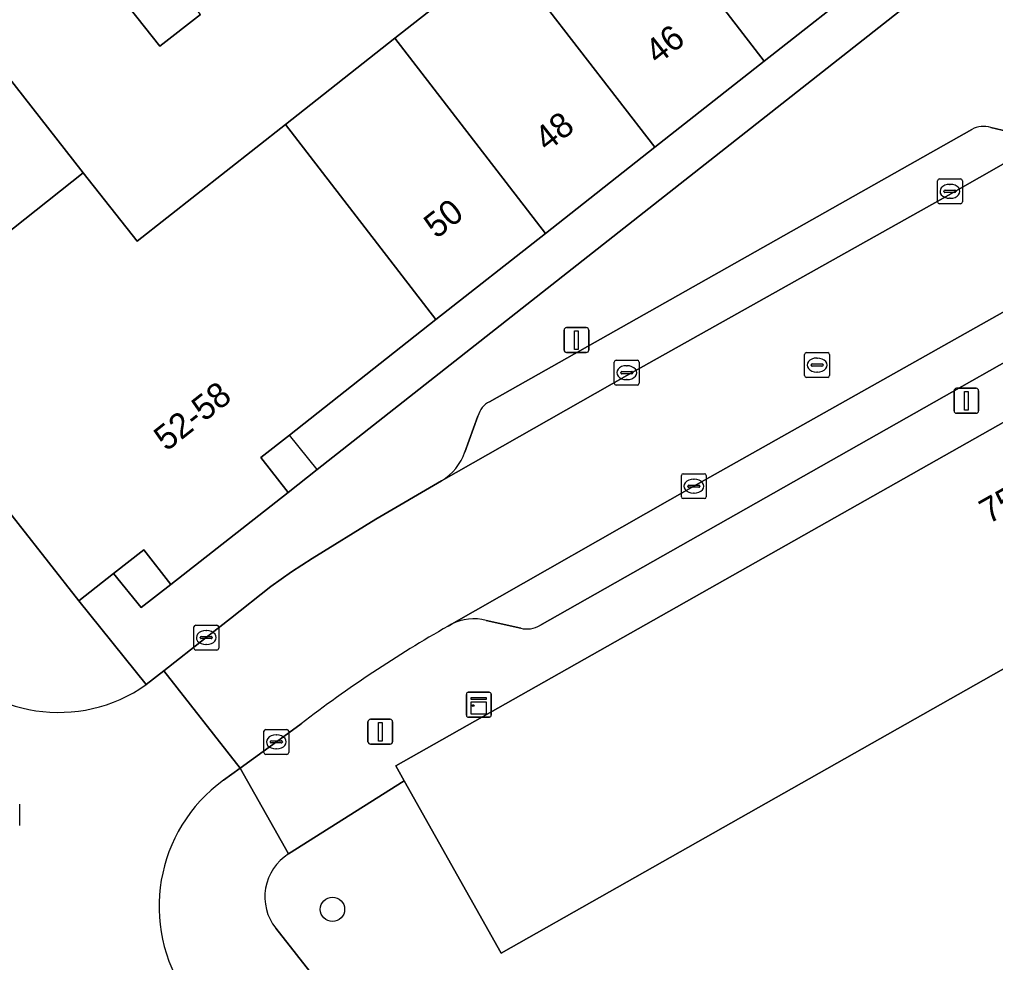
# Model space of a CAD drawing. Extents: x 160377 to 161131, y 383938 to 384853.
# Drawn here: x 160793.66 to 160832.91, y 384332.45 to 384370.35 of the extents above; entities that cross this region are included whole.
import ezdxf

# ---------------------------------------------------------------- set-up
doc = ezdxf.new("R2010")
doc.units = 0
for name, color, linetype in [('IMGEO_Boom', 7, 'Continuous'), ('IMGEO_Erf', 7, 'Continuous'), ('IMGEO_Kast', 7, 'Continuous'), ('IMGEO_Kolk', 7, 'Continuous'), ('IMGEO_Lichtmast', 7, 'Continuous'), ('IMGEO_Pand', 7, 'Continuous'), ('IMGEO_Pand_nummerreeks', 7, 'Continuous'), ('IMGEO_Pand_overbouw', 7, 'Continuous'), ('IMGEO_Parkeervlak_open', 7, 'Continuous'), ('IMGEO_Rijbaan_lokaal_open', 7, 'Continuous'), ('IMGEO_Rioolput', 7, 'Continuous'), ('IMGEO_Voetpad_open', 7, 'Continuous')]:
    doc.layers.add(name, color=color, linetype=linetype)

msp = doc.modelspace()

# ---------------------------------------------------------------- linework, layer by layer
at = {"layer": 'IMGEO_Boom'}
msp.add_circle((160806.245, 384334.579), 0.489, dxfattribs=at)
at = {"layer": 'IMGEO_Erf'}
for points in [[(160833.751, 384374.399), (160832.651, 384375.795), (160828.01, 384372.142), (160823.609, 384368.678), (160819.208, 384365.214), (160814.808, 384361.751), (160810.407, 384358.287), (160804.513, 384353.647), (160803.366, 384352.745), (160804.464, 384351.34), (160805.632, 384352.26)], [(160798.654, 384349.037), (160797.435, 384348.078), (160798.55, 384346.709), (160799.746, 384347.64)]]:
    msp.add_lwpolyline(points, close=True, dxfattribs=at)
for points in [[(160792.762, 384368.592), (160796.225, 384364.19), (160798.39, 384361.439), (160804.353, 384366.133), (160808.754, 384369.597), (160813.155, 384373.06)], [(160800.939, 384370.558), (160799.307, 384369.274), (160797.763, 384371.239)], [(160864.012, 384361.665), (160817.378, 384335.283), (160813.026, 384332.821), (160809.131, 384339.748), (160804.478, 384336.81)], [(160803.961, 384333.818), (160807.286, 384329.584), (160806.969, 384329.33), (160807.38, 384328.806), (160807.698, 384329.059), (160810.129, 384325.962), (160809.812, 384325.71), (160810.233, 384325.182), (160810.55, 384325.434), (160823.97, 384308.474), (160823.653, 384308.221), (160824.106, 384307.637), (160824.656, 384308.075), (160824.527, 384308.24), (160824.985, 384308.54), (160827.264, 384305.335), (160831.604, 384307.819), (160838.184, 384311.586)]]:
    msp.add_lwpolyline(points, dxfattribs=at)
msp.add_arc((160805.571, 384335.08), 2.046, 122.2944, 218.0984, dxfattribs=at)
at = {"layer": 'IMGEO_Kast'}
for p, q in [((160811.628, 384342.381), (160811.628, 384343.222)), ((160811.628, 384343.222), (160811.628, 384342.381)), ((160811.703, 384343.306), (160812.544, 384343.306)), ((160812.544, 384343.306), (160811.703, 384343.306)), ((160812.628, 384343.231), (160812.628, 384342.39)), ((160812.628, 384342.39), (160812.628, 384343.231)), ((160812.553, 384342.306), (160811.712, 384342.306)), ((160811.712, 384342.306), (160812.553, 384342.306))]:
    msp.add_line(p, q, dxfattribs=at)
for points in [[(160811.823, 384343.096), (160812.423, 384343.096), (160812.423, 384343.011), (160811.823, 384343.011), (160811.823, 384343.096)], [(160811.823, 384342.921), (160812.423, 384342.921), (160812.423, 384342.432), (160811.823, 384342.432), (160811.823, 384342.921)]]:
    msp.add_lwpolyline(points, dxfattribs=at)
msp.add_circle((160811.907, 384342.77), 0.0377, dxfattribs=at)
for centre, start, end in [((160811.706, 384343.228), 92.4484, 184.2845), ((160811.706, 384343.228), 92.4484, 184.2845), ((160812.55, 384343.228), 2.4484, 94.2845), ((160812.55, 384343.228), 2.4484, 94.2845), ((160811.706, 384342.384), 182.4484, 274.2845), ((160811.706, 384342.384), 182.4484, 274.2845), ((160812.55, 384342.384), 272.4484, 4.2845), ((160812.55, 384342.384), 272.4484, 4.2845)]:
    msp.add_arc(centre, 0.0779, start, end, dxfattribs=at)
at = {"layer": 'IMGEO_Kolk'}
for p, q in [((160830.575, 384363.018), (160830.575, 384363.87)), ((160830.65, 384363.944), (160831.502, 384363.944)), ((160831.576, 384363.87), (160831.576, 384363.018)), ((160830.834, 384363.438), (160830.834, 384363.45)), ((160831.272, 384363.401), (160830.874, 384363.401)), ((160830.877, 384363.487), (160831.275, 384363.487)), ((160831.063, 384363.724), (160831.088, 384363.724)), ((160831.318, 384363.45), (160831.318, 384363.438)), ((160831.086, 384363.164), (160831.061, 384363.164)), ((160831.502, 384362.944), (160830.65, 384362.944)), ((160817.577, 384355.728), (160817.577, 384356.58)), ((160817.652, 384356.654), (160818.504, 384356.654)), ((160818.065, 384356.434), (160818.09, 384356.434)), ((160818.578, 384356.58), (160818.578, 384355.728)), ((160817.836, 384356.148), (160817.836, 384356.16)), ((160818.274, 384356.111), (160817.876, 384356.111)), ((160817.879, 384356.197), (160818.277, 384356.197)), ((160818.32, 384356.16), (160818.32, 384356.148)), ((160818.504, 384355.654), (160817.652, 384355.654)), ((160818.088, 384355.874), (160818.063, 384355.874)), ((160820.276, 384351.164), (160820.276, 384352.016)), ((160820.351, 384352.09), (160821.203, 384352.09)), ((160821.277, 384352.016), (160821.277, 384351.164)), ((160820.535, 384351.584), (160820.535, 384351.596)), ((160820.578, 384351.633), (160820.976, 384351.633)), ((160820.764, 384351.87), (160820.789, 384351.87)), ((160821.019, 384351.596), (160821.019, 384351.584)), ((160820.973, 384351.547), (160820.575, 384351.547)), ((160820.787, 384351.31), (160820.762, 384351.31)), ((160821.203, 384351.09), (160820.351, 384351.09)), ((160800.67, 384345.079), (160800.67, 384345.931)), ((160800.745, 384346.005), (160801.597, 384346.005)), ((160801.158, 384345.785), (160801.183, 384345.785)), ((160801.671, 384345.931), (160801.671, 384345.079)), ((160800.929, 384345.499), (160800.929, 384345.511)), ((160801.367, 384345.462), (160800.969, 384345.462)), ((160800.972, 384345.548), (160801.37, 384345.548)), ((160801.413, 384345.511), (160801.413, 384345.499)), ((160801.597, 384345.005), (160800.745, 384345.005)), ((160801.181, 384345.225), (160801.156, 384345.225)), ((160803.561, 384341.811), (160804.413, 384341.811)), ((160803.486, 384340.885), (160803.486, 384341.737)), ((160803.974, 384341.591), (160803.999, 384341.591)), ((160804.487, 384341.737), (160804.487, 384340.885)), ((160803.745, 384341.305), (160803.745, 384341.317)), ((160804.183, 384341.268), (160803.785, 384341.268)), ((160803.788, 384341.354), (160804.186, 384341.354)), ((160803.997, 384341.031), (160803.972, 384341.031)), ((160804.229, 384341.317), (160804.229, 384341.305)), ((160804.413, 384340.811), (160803.561, 384340.811))]:
    msp.add_line(p, q, dxfattribs=at)
for points in [[(160830.575, 384363.018), (160830.575, 384363.87)], [(160830.65, 384363.944), (160831.502, 384363.944)], [(160831.576, 384363.87), (160831.576, 384363.018)], [(160831.502, 384362.944), (160830.65, 384362.944)], [(160817.577, 384355.728), (160817.577, 384356.58)], [(160817.652, 384356.654), (160818.504, 384356.654)], [(160818.578, 384356.58), (160818.578, 384355.728)], [(160818.504, 384355.654), (160817.652, 384355.654)], [(160820.276, 384351.164), (160820.276, 384352.016)], [(160820.351, 384352.09), (160821.203, 384352.09)], [(160821.277, 384352.016), (160821.277, 384351.164)], [(160821.203, 384351.09), (160820.351, 384351.09)], [(160800.67, 384345.079), (160800.67, 384345.931)], [(160800.745, 384346.005), (160801.597, 384346.005)], [(160801.671, 384345.931), (160801.671, 384345.079)], [(160801.597, 384345.005), (160800.745, 384345.005)], [(160803.561, 384341.811), (160804.413, 384341.811)], [(160803.486, 384340.885), (160803.486, 384341.737)], [(160804.487, 384341.737), (160804.487, 384340.885)], [(160804.413, 384340.811), (160803.561, 384340.811)]]:
    msp.add_lwpolyline(points, dxfattribs=at)
for centre, radius, start, end in [((160830.652, 384363.868), 0.0765, 91.552, 178.448), ((160830.652, 384363.868), 0.0765, 91.552, 178.448), ((160831.5, 384363.868), 0.0765, 1.552, 88.448), ((160831.5, 384363.868), 0.0765, 1.552, 88.448), ((160830.874, 384363.447), 0.0403, 85.8775, 175.7526), ((160830.871, 384363.437), 0.0366, 178.938, 274.7102), ((160831.275, 384363.444), 0.043, 264.8664, 352.4533), ((160831.279, 384363.449), 0.0386, 1.7309, 96.639), ((160830.652, 384363.02), 0.0765, 181.552, 268.448), ((160830.652, 384363.02), 0.0765, 181.552, 268.448), ((160831.5, 384363.02), 0.0765, 271.552, 358.448), ((160831.5, 384363.02), 0.0765, 271.552, 358.448), ((160817.654, 384356.578), 0.0765, 91.552, 178.448), ((160817.654, 384356.578), 0.0765, 91.552, 178.448), ((160818.502, 384356.578), 0.0765, 1.552, 88.448), ((160818.502, 384356.578), 0.0765, 1.552, 88.448), ((160817.876, 384356.157), 0.0403, 85.8775, 175.7526), ((160817.873, 384356.147), 0.0366, 178.938, 274.7102), ((160818.277, 384356.154), 0.043, 264.8664, 352.4533), ((160818.281, 384356.159), 0.0386, 1.7309, 96.639), ((160817.654, 384355.73), 0.0765, 181.552, 268.448), ((160817.654, 384355.73), 0.0765, 181.552, 268.448), ((160818.502, 384355.73), 0.0765, 271.552, 358.448), ((160818.502, 384355.73), 0.0765, 271.552, 358.448), ((160820.353, 384352.014), 0.0765, 91.552, 178.448), ((160820.353, 384352.014), 0.0765, 91.552, 178.448), ((160821.201, 384352.014), 0.0765, 1.552, 88.448), ((160821.201, 384352.014), 0.0765, 1.552, 88.448), ((160820.575, 384351.593), 0.0403, 85.8775, 175.7526), ((160820.98, 384351.595), 0.0386, 1.7309, 96.639), ((160820.572, 384351.583), 0.0366, 178.938, 274.7102), ((160820.976, 384351.59), 0.043, 264.8664, 352.4533), ((160820.353, 384351.166), 0.0765, 181.552, 268.448), ((160820.353, 384351.166), 0.0765, 181.552, 268.448), ((160821.201, 384351.166), 0.0765, 271.552, 358.448), ((160821.201, 384351.166), 0.0765, 271.552, 358.448), ((160800.747, 384345.929), 0.0765, 91.552, 178.448), ((160800.747, 384345.929), 0.0765, 91.552, 178.448), ((160801.595, 384345.929), 0.0765, 1.552, 88.448), ((160801.595, 384345.929), 0.0765, 1.552, 88.448), ((160800.969, 384345.508), 0.0403, 85.8775, 175.7526), ((160800.966, 384345.498), 0.0366, 178.938, 274.7102), ((160801.37, 384345.505), 0.043, 264.8664, 352.4533), ((160801.374, 384345.51), 0.0386, 1.7309, 96.639), ((160800.747, 384345.081), 0.0765, 181.552, 268.448), ((160800.747, 384345.081), 0.0765, 181.552, 268.448), ((160801.595, 384345.081), 0.0765, 271.552, 358.448), ((160801.595, 384345.081), 0.0765, 271.552, 358.448), ((160803.563, 384341.735), 0.0765, 91.552, 178.448), ((160803.563, 384341.735), 0.0765, 91.552, 178.448), ((160804.411, 384341.735), 0.0765, 1.552, 88.448), ((160804.411, 384341.735), 0.0765, 1.552, 88.448), ((160803.785, 384341.314), 0.0403, 85.8775, 175.7526), ((160803.782, 384341.304), 0.0366, 178.938, 274.7102), ((160804.186, 384341.311), 0.043, 264.8664, 352.4533), ((160804.19, 384341.316), 0.0386, 1.7309, 96.639), ((160803.563, 384340.887), 0.0765, 181.552, 268.448), ((160803.563, 384340.887), 0.0765, 181.552, 268.448), ((160804.411, 384340.887), 0.0765, 271.552, 358.448), ((160804.411, 384340.887), 0.0765, 271.552, 358.448)]:
    msp.add_arc(centre, radius, start, end, dxfattribs=at)
for centre, major_axis, ratio, start_param, end_param in [((160831.062, 384363.444), (-0.387, 0.002), 0.722429, 4.712389, 7.853982), ((160831.087, 384363.444), (-0.39, 0.002), 0.717154, 1.570796, 4.712389), ((160818.064, 384356.154), (-0.387, 0.002), 0.722429, 4.712389, 7.853982), ((160818.089, 384356.154), (-0.39, 0.002), 0.717154, 1.570796, 4.712389), ((160820.763, 384351.59), (-0.387, 0.002), 0.722429, 4.712389, 7.853982), ((160820.788, 384351.59), (-0.39, 0.002), 0.717154, 1.570796, 4.712389), ((160801.157, 384345.505), (-0.387, 0.002), 0.722429, 4.712389, 7.853982), ((160801.182, 384345.505), (-0.39, 0.002), 0.717154, 1.570796, 4.712389), ((160803.973, 384341.311), (-0.387, 0.002), 0.722429, 4.712389, 7.853982), ((160803.998, 384341.311), (-0.39, 0.002), 0.717154, 1.570796, 4.712389)]:
    msp.add_ellipse(centre, major_axis=major_axis, ratio=ratio, start_param=start_param, end_param=end_param, dxfattribs=at)
at = {"layer": 'IMGEO_Lichtmast'}
for p, q in [((160815.56, 384357.065), (160815.56, 384357.865)), ((160815.56, 384357.865), (160815.56, 384357.065)), ((160815.66, 384357.965), (160816.45, 384357.965)), ((160816.45, 384357.965), (160815.66, 384357.965)), ((160816.55, 384357.865), (160816.55, 384357.065)), ((160816.55, 384357.065), (160816.55, 384357.865)), ((160816.45, 384356.965), (160815.66, 384356.965)), ((160815.66, 384356.965), (160816.45, 384356.965)), ((160831.339, 384355.525), (160832.129, 384355.525)), ((160832.129, 384355.525), (160831.339, 384355.525)), ((160831.239, 384354.625), (160831.239, 384355.425)), ((160831.239, 384355.425), (160831.239, 384354.625)), ((160832.229, 384355.425), (160832.229, 384354.625)), ((160832.229, 384354.625), (160832.229, 384355.425)), ((160832.129, 384354.525), (160831.339, 384354.525)), ((160831.339, 384354.525), (160832.129, 384354.525)), ((160807.771, 384342.221), (160808.561, 384342.221)), ((160808.561, 384342.221), (160807.771, 384342.221)), ((160807.671, 384341.321), (160807.671, 384342.121)), ((160807.671, 384342.121), (160807.671, 384341.321)), ((160808.661, 384342.121), (160808.661, 384341.321)), ((160808.661, 384341.321), (160808.661, 384342.121)), ((160808.561, 384341.221), (160807.771, 384341.221)), ((160807.771, 384341.221), (160808.561, 384341.221))]:
    msp.add_line(p, q, dxfattribs=at)
for points in [[(160815.98, 384357.84), (160816.13, 384357.84), (160816.13, 384357.09), (160815.98, 384357.09), (160815.98, 384357.84)], [(160831.659, 384355.4), (160831.809, 384355.4), (160831.809, 384354.65), (160831.659, 384354.65), (160831.659, 384355.4)], [(160808.091, 384342.096), (160808.241, 384342.096), (160808.241, 384341.346), (160808.091, 384341.346), (160808.091, 384342.096)]]:
    msp.add_lwpolyline(points, dxfattribs=at)
for centre, start, end in [((160815.66, 384357.865), 90, 180), ((160815.66, 384357.865), 90, 180), ((160816.45, 384357.865), 0, 90), ((160816.45, 384357.865), 360, 90), ((160815.66, 384357.065), 180, 270), ((160815.66, 384357.065), 180, 270), ((160816.45, 384357.065), 270, 0), ((160816.45, 384357.065), 270, 0), ((160831.339, 384355.425), 90, 180), ((160831.339, 384355.425), 90, 180), ((160832.129, 384355.425), 0, 90), ((160832.129, 384355.425), 360, 90), ((160831.339, 384354.625), 180, 270), ((160831.339, 384354.625), 180, 270), ((160832.129, 384354.625), 270, 0), ((160832.129, 384354.625), 270, 0), ((160807.771, 384342.121), 90, 180), ((160807.771, 384342.121), 90, 180), ((160808.561, 384342.121), 0, 90), ((160808.561, 384342.121), 360, 90), ((160807.771, 384341.321), 180, 270), ((160807.771, 384341.321), 180, 270), ((160808.561, 384341.321), 270, 0), ((160808.561, 384341.321), 270, 0)]:
    msp.add_arc(centre, 0.1, start, end, dxfattribs=at)
at = {"layer": 'IMGEO_Pand'}
for points in [[(160828.01, 384372.142), (160821.956, 384379.988), (160817.555, 384376.524), (160823.609, 384368.678)], [(160823.609, 384368.678), (160817.555, 384376.524), (160813.155, 384373.06), (160819.208, 384365.214)], [(160814.808, 384361.751), (160819.208, 384365.214), (160813.155, 384373.06), (160808.754, 384369.597)], [(160799.413, 384372.536), (160797.763, 384371.239), (160799.307, 384369.274), (160800.939, 384370.558)], [(160814.808, 384361.751), (160808.754, 384369.597), (160804.353, 384366.133), (160810.407, 384358.287)], [(160864.012, 384361.665), (160863.497, 384362.573), (160862.231, 384364.807), (160859.765, 384369.156), (160808.792, 384340.351), (160809.131, 384339.748), (160813.026, 384332.821), (160817.378, 384335.283)], [(160789.169, 384358.606), (160796.225, 384364.19), (160792.762, 384368.592), (160785.706, 384363.006)], [(160789.169, 384358.606), (160791.33, 384355.859), (160789.93, 384354.754), (160796.051, 384346.989), (160797.435, 384348.078), (160798.654, 384349.037), (160799.746, 384347.64), (160804.464, 384351.34), (160803.366, 384352.745), (160804.513, 384353.647), (160810.407, 384358.287), (160804.353, 384366.133), (160798.39, 384361.439), (160796.225, 384364.19)]]:
    msp.add_lwpolyline(points, close=True, dxfattribs=at)
at = {"layer": 'IMGEO_Pand_overbouw'}
for points in [[(160804.513, 384353.647), (160803.366, 384352.745), (160804.464, 384351.34), (160805.632, 384352.26)], [(160798.654, 384349.037), (160797.435, 384348.078), (160798.55, 384346.709), (160799.746, 384347.64)]]:
    msp.add_lwpolyline(points, close=True, dxfattribs=at)
at = {"layer": 'IMGEO_Parkeervlak_open'}
for points in [[(160810.632, 384351.812), (160818.08, 384356.037), (160831.014, 384363.292), (160844.726, 384371.099), (160848.553, 384373.24)], [(160851.223, 384368.679), (160847.309, 384366.563), (160833.622, 384358.814), (160820.772, 384351.591), (160811.035, 384346.043)], [(160831.953, 384365.934), (160812.565, 384354.987)], [(160814.588, 384345.994), (160850.035, 384366.061)], [(160833.627, 384365.792), (160832.715, 384366.006)], [(160812.094, 384354.411), (160811.572, 384352.965)], [(160812.425, 384346.196), (160813.818, 384345.88)]]:
    msp.add_lwpolyline(points, dxfattribs=at)
for centre, radius, start, end in [((160832.419, 384365.066), 0.986, 72.5541, 118.2414), ((160812.982, 384354.166), 0.921, 116.9009, 164.5528), ((160809.554, 384353.651), 2.131, 300.3857, 341.236), ((160811.928, 384344.319), 1.942, 75.1759, 117.3868), ((160814.06, 384346.901), 1.05, 256.6597, 300.1834)]:
    msp.add_arc(centre, radius, start, end, dxfattribs=at)
at = {"layer": 'IMGEO_Rijbaan_lokaal_open'}
for points in [[(160820.772, 384351.591), (160833.622, 384358.814), (160847.309, 384366.563), (160851.223, 384368.679), (160848.553, 384373.24), (160844.726, 384371.099), (160831.014, 384363.292), (160818.08, 384356.037), (160810.632, 384351.812), (160807.988, 384350.266), (160805.432, 384348.679), (160804.592, 384348.142), (160803.768, 384347.553), (160802.15, 384346.266), (160801.171, 384345.505), (160799.467, 384344.172), (160802.531, 384340.254), (160803.987, 384341.311), (160804.982, 384342.038)], [(160810.894, 384345.963), (160811.035, 384346.043), (160820.772, 384351.591)], [(160802.531, 384340.254), (160799.467, 384344.172), (160798.752, 384343.613)], [(160801.863, 384339.769), (160802.531, 384340.254)]]:
    msp.add_lwpolyline(points, dxfattribs=at)
for centre, radius, start, end in [((160835.93, 384301.838), 50.733, 119.5699, 127.5908), ((160795.234, 384348.6), 6.103, 217.4834, 305.2025), ((160805.525, 384334.699), 6.254, 125.8393, 214.8428)]:
    msp.add_arc(centre, radius, start, end, dxfattribs=at)
at = {"layer": 'IMGEO_Rioolput'}
for p, q in [((160825.231, 384356.034), (160825.231, 384356.886)), ((160825.306, 384356.96), (160826.158, 384356.96)), ((160825.719, 384356.74), (160825.744, 384356.74)), ((160826.232, 384356.886), (160826.232, 384356.034)), ((160825.49, 384356.454), (160825.49, 384356.466)), ((160825.928, 384356.417), (160825.53, 384356.417)), ((160825.533, 384356.503), (160825.931, 384356.503)), ((160825.974, 384356.466), (160825.974, 384356.454)), ((160826.158, 384355.96), (160825.306, 384355.96)), ((160825.742, 384356.18), (160825.717, 384356.18)), ((160793.659, 384338.804), (160793.659, 384337.952))]:
    msp.add_line(p, q, dxfattribs=at)
for points in [[(160825.231, 384356.034), (160825.231, 384356.886)], [(160825.306, 384356.96), (160826.158, 384356.96)], [(160826.232, 384356.886), (160826.232, 384356.034)], [(160826.158, 384355.96), (160825.306, 384355.96)], [(160793.659, 384338.804), (160793.659, 384337.952)]]:
    msp.add_lwpolyline(points, dxfattribs=at)
for centre, radius, start, end in [((160825.308, 384356.884), 0.0765, 91.552, 178.448), ((160825.308, 384356.884), 0.0765, 91.552, 178.448), ((160826.156, 384356.884), 0.0765, 1.552, 88.448), ((160826.156, 384356.884), 0.0765, 1.552, 88.448), ((160825.53, 384356.463), 0.0403, 85.8775, 175.7526), ((160825.527, 384356.453), 0.0366, 178.938, 274.7102), ((160825.931, 384356.46), 0.043, 264.8664, 352.4533), ((160825.935, 384356.465), 0.0386, 1.7309, 96.639), ((160825.308, 384356.036), 0.0765, 181.552, 268.448), ((160825.308, 384356.036), 0.0765, 181.552, 268.448), ((160826.156, 384356.036), 0.0765, 271.552, 358.448), ((160826.156, 384356.036), 0.0765, 271.552, 358.448)]:
    msp.add_arc(centre, radius, start, end, dxfattribs=at)
for centre, major_axis, ratio, start_param, end_param in [((160825.718, 384356.46), (-0.387, 0.002), 0.722429, 4.712389, 7.853982), ((160825.743, 384356.46), (-0.39, 0.002), 0.717154, 1.570796, 4.712389)]:
    msp.add_ellipse(centre, major_axis=major_axis, ratio=ratio, start_param=start_param, end_param=end_param, dxfattribs=at)
at = {"layer": 'IMGEO_Voetpad_open'}
for points in [[(160851.885, 384388.225), (160851.673, 384388.488), (160848.557, 384386.056), (160834.888, 384375.294), (160833.751, 384374.399), (160805.632, 384352.26), (160804.464, 384351.34), (160799.746, 384347.64), (160798.55, 384346.709), (160797.435, 384348.078), (160796.051, 384346.989), (160798.752, 384343.613), (160799.467, 384344.172), (160801.171, 384345.505), (160802.15, 384346.266), (160803.768, 384347.553), (160804.592, 384348.142), (160805.432, 384348.679), (160807.988, 384350.266), (160810.632, 384351.812)], [(160798.752, 384343.613), (160796.051, 384346.989), (160789.93, 384354.754), (160764.882, 384386.58)], [(160804.982, 384342.038), (160803.987, 384341.311), (160802.531, 384340.254), (160804.478, 384336.81), (160809.131, 384339.748), (160808.792, 384340.351), (160859.765, 384369.156), (160861.401, 384370.087), (160865.994, 384372.648), (160870.638, 384375.237), (160871.943, 384375.973), (160873.248, 384376.708), (160877.762, 384379.261), (160882.393, 384381.879)], [(160812.565, 384354.987), (160831.953, 384365.934)], [(160850.035, 384366.061), (160814.588, 384345.994)], [(160832.715, 384366.006), (160833.627, 384365.792)], [(160811.572, 384352.965), (160812.094, 384354.411)], [(160813.818, 384345.88), (160812.425, 384346.196)], [(160811.035, 384346.043), (160810.894, 384345.963)], [(160804.478, 384336.81), (160802.531, 384340.254), (160801.863, 384339.769)], [(160838.654, 384287.235), (160835.229, 384293.141), (160831.684, 384299.256), (160831.111, 384300.243), (160827.264, 384305.335), (160824.985, 384308.54), (160824.527, 384308.24), (160824.656, 384308.075), (160824.106, 384307.637), (160823.653, 384308.221), (160823.97, 384308.474), (160810.55, 384325.434), (160810.233, 384325.182), (160809.812, 384325.71), (160810.129, 384325.962), (160807.698, 384329.059), (160807.38, 384328.806), (160806.969, 384329.33), (160807.286, 384329.584), (160803.961, 384333.818)]]:
    msp.add_lwpolyline(points, dxfattribs=at)
for centre, radius, start, end in [((160832.419, 384365.066), 0.986, 72.5541, 118.2414), ((160812.982, 384354.166), 0.921, 116.9009, 164.5528), ((160809.554, 384353.651), 2.131, 300.3857, 341.236), ((160811.928, 384344.319), 1.942, 75.1759, 117.3868), ((160835.93, 384301.838), 50.733, 119.5699, 127.5908), ((160814.06, 384346.901), 1.05, 256.6597, 300.1834), ((160795.234, 384348.6), 6.103, 217.4834, 305.2025), ((160805.525, 384334.699), 6.254, 125.8393, 214.8428), ((160805.571, 384335.08), 2.046, 122.2944, 218.0984)]:
    msp.add_arc(centre, radius, start, end, dxfattribs=at)

# ---------------------------------------------------------------- texts
at = {"layer": 'IMGEO_Pand_nummerreeks'}
for s, rotation, p in [('46', 38.2059, (160819.32, 384368.51)), ('48', 38.2059, (160814.875, 384365.01)), ('50', 38.2059, (160810.426, 384361.509)), ('52-58', 38.2023, (160799.57, 384352.965)), ('75A-75F', 29.4036, (160832.63, 384350.053))]:
    msp.add_text(s, height=1, rotation=rotation, dxfattribs=at).set_placement(p)

doc.saveas('drawing.dxf')
